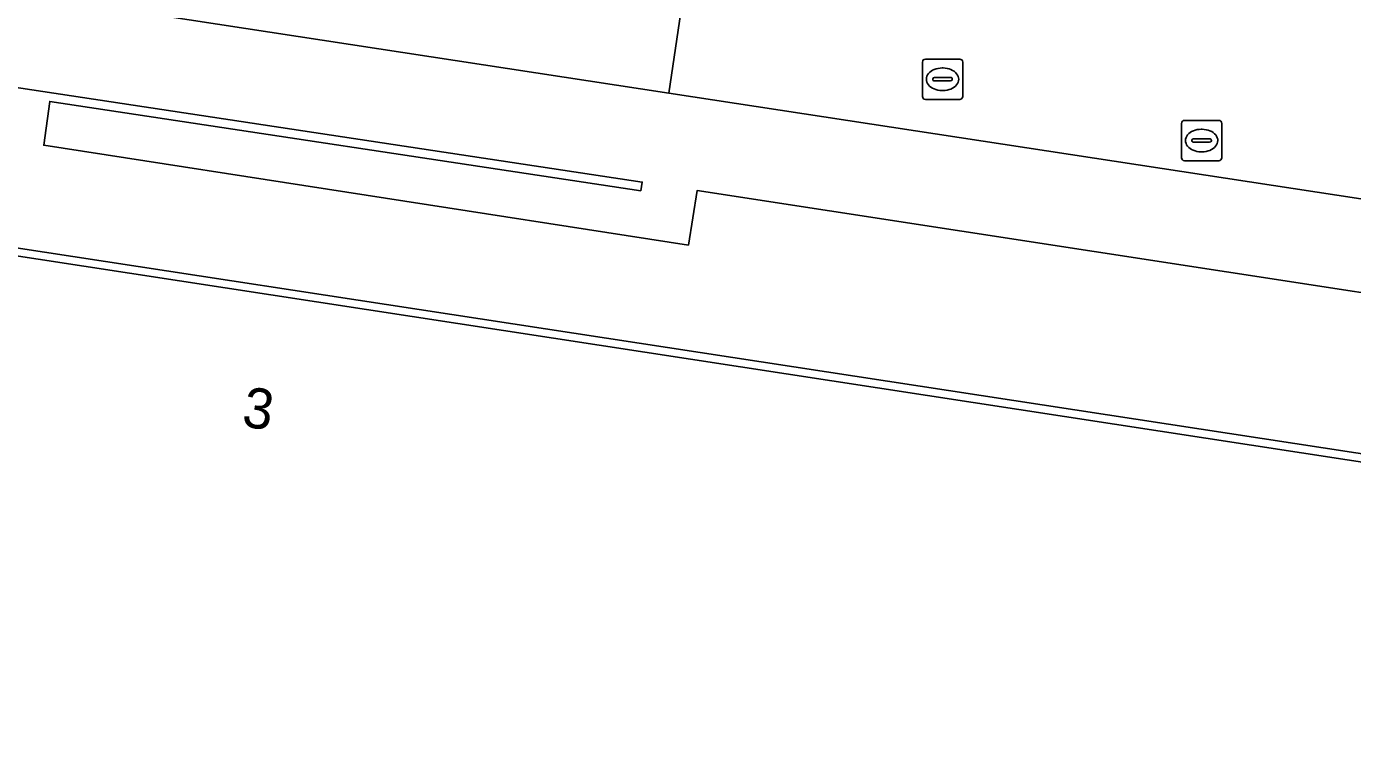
# Model space of a CAD drawing. Extents: x 161090 to 161692, y 379509 to 380907.
# Drawn here: x 161426.27 to 161459.19, y 380421.99 to 380439.9 of the extents above; entities that cross this region are included whole.
import ezdxf

# ---------------------------------------------------------------- set-up
doc = ezdxf.new("R2010")
doc.units = 0
for name, color, linetype in [('IMGEO_Groenvoorziening', 7, 'Continuous'), ('IMGEO_Pand', 7, 'Continuous'), ('IMGEO_Pand_nummerreeks', 7, 'Continuous'), ('IMGEO_Pand_overbouw', 7, 'Continuous'), ('IMGEO_Rioolput', 7, 'Continuous'), ('IMGEO_Voetpad_gesloten', 7, 'Continuous'), ('IMGEO_Voetpad_open', 7, 'Continuous')]:
    doc.layers.add(name, color=color, linetype=linetype)

msp = doc.modelspace()

# ---------------------------------------------------------------- linework, layer by layer
at = {"layer": 'IMGEO_Groenvoorziening'}
msp.add_lwpolyline([(161493.731, 380423.528), (161495.965, 380438.206), (161443.393, 380446.183), (161442.217, 380438.238), (161478.261, 380432.731), (161477.122, 380425.066), (161489.343, 380423.181), (161491.526, 380422.852)], dxfattribs=at)
at = {"layer": 'IMGEO_Pand'}
msp.add_lwpolyline([(161415.881, 380435.194), (161415.964, 380435.735), (161391.176, 380439.506), (161383.009, 380385.949), (161464.836, 380373.488), (161472.988, 380426.991), (161418.398, 380435.368), (161418.318, 380434.848)], dxfattribs=at)
at = {"layer": 'IMGEO_Pand_overbouw'}
msp.add_lwpolyline([(161458.223, 380370.06), (161464.36, 380369.123), (161473.226, 380427.168), (161391.017, 380439.754), (161382.131, 380381.674), (161399.864, 380378.968), (161426.096, 380374.964), (161453.543, 380370.774)], close=True, dxfattribs=at)
msp.add_lwpolyline([(161418.318, 380434.848), (161418.398, 380435.368), (161472.988, 380426.991), (161464.836, 380373.488), (161383.009, 380385.949), (161391.176, 380439.506), (161415.964, 380435.735), (161415.881, 380435.194)], dxfattribs=at)
at = {"layer": 'IMGEO_Rioolput'}
for p, q in [((161448.512, 380438.16), (161448.512, 380439.012)), ((161448.587, 380439.086), (161449.439, 380439.086)), ((161449, 380438.866), (161449.025, 380438.866)), ((161449.513, 380439.012), (161449.513, 380438.16)), ((161448.771, 380438.58), (161448.771, 380438.592)), ((161449.209, 380438.543), (161448.811, 380438.543)), ((161448.814, 380438.629), (161449.212, 380438.629)), ((161449.255, 380438.592), (161449.255, 380438.58)), ((161449.023, 380438.306), (161448.998, 380438.306)), ((161449.439, 380438.086), (161448.587, 380438.086)), ((161454.944, 380436.637), (161454.944, 380437.489)), ((161455.019, 380437.563), (161455.871, 380437.563)), ((161455.945, 380437.489), (161455.945, 380436.637)), ((161455.432, 380437.343), (161455.457, 380437.343)), ((161455.203, 380437.057), (161455.203, 380437.069)), ((161455.641, 380437.02), (161455.243, 380437.02)), ((161455.246, 380437.106), (161455.644, 380437.106)), ((161455.455, 380436.783), (161455.43, 380436.783)), ((161455.687, 380437.069), (161455.687, 380437.057)), ((161455.871, 380436.563), (161455.019, 380436.563))]:
    msp.add_line(p, q, dxfattribs=at)
for points in [[(161448.512, 380438.16), (161448.512, 380439.012)], [(161448.587, 380439.086), (161449.439, 380439.086)], [(161449.513, 380439.012), (161449.513, 380438.16)], [(161449.439, 380438.086), (161448.587, 380438.086)], [(161454.944, 380436.637), (161454.944, 380437.489)], [(161455.019, 380437.563), (161455.871, 380437.563)], [(161455.945, 380437.489), (161455.945, 380436.637)], [(161455.871, 380436.563), (161455.019, 380436.563)]]:
    msp.add_lwpolyline(points, dxfattribs=at)
for centre, radius, start, end in [((161448.589, 380439.01), 0.0765, 91.552, 178.448), ((161448.589, 380439.01), 0.0765, 91.552, 178.448), ((161449.437, 380439.01), 0.0765, 1.552, 88.448), ((161449.437, 380439.01), 0.0765, 1.552, 88.448), ((161448.811, 380438.589), 0.0403, 85.8775, 175.7526), ((161448.808, 380438.579), 0.0366, 178.938, 274.7102), ((161449.212, 380438.586), 0.043, 264.8664, 352.4533), ((161449.216, 380438.591), 0.0386, 1.7309, 96.639), ((161448.589, 380438.162), 0.0765, 181.552, 268.448), ((161448.589, 380438.162), 0.0765, 181.552, 268.448), ((161449.437, 380438.162), 0.0765, 271.552, 358.448), ((161449.437, 380438.162), 0.0765, 271.552, 358.448), ((161455.021, 380437.487), 0.0765, 91.552, 178.448), ((161455.021, 380437.487), 0.0765, 91.552, 178.448), ((161455.869, 380437.487), 0.0765, 1.552, 88.448), ((161455.869, 380437.487), 0.0765, 1.552, 88.448), ((161455.243, 380437.066), 0.0403, 85.8775, 175.7526), ((161455.24, 380437.056), 0.0366, 178.938, 274.7102), ((161455.644, 380437.063), 0.043, 264.8664, 352.4533), ((161455.648, 380437.068), 0.0386, 1.7309, 96.639), ((161455.021, 380436.639), 0.0765, 181.552, 268.448), ((161455.021, 380436.639), 0.0765, 181.552, 268.448), ((161455.869, 380436.639), 0.0765, 271.552, 358.448), ((161455.869, 380436.639), 0.0765, 271.552, 358.448)]:
    msp.add_arc(centre, radius, start, end, dxfattribs=at)
for centre, major_axis, ratio, start_param, end_param in [((161448.999, 380438.586), (-0.387, 0.002), 0.722429, 4.712389, 7.853982), ((161449.024, 380438.586), (-0.39, 0.002), 0.717154, 1.570796, 4.712389), ((161455.431, 380437.063), (-0.387, 0.002), 0.722429, 4.712389, 7.853982), ((161455.456, 380437.063), (-0.39, 0.002), 0.717154, 1.570796, 4.712389)]:
    msp.add_ellipse(centre, major_axis=major_axis, ratio=ratio, start_param=start_param, end_param=end_param, dxfattribs=at)
at = {"layer": 'IMGEO_Voetpad_gesloten'}
msp.add_lwpolyline([(161408.715, 380456.21), (161409.175, 380459.263), (161409.326, 380460.065), (161407.756, 380460.303), (161407.057, 380455.696), (161406.698, 380453.806), (161406.57, 380452.878), (161406.436, 380451.901), (161405.596, 380445.799), (161405.292, 380443.896), (161442.217, 380438.238), (161443.393, 380446.183), (161443.671, 380448.06), (161443.979, 380450.12), (161444.743, 380454.689), (161442.833, 380454.979), (161442.709, 380453.98), (161442.237, 380450.876)], dxfattribs=at)
msp.add_lwpolyline([(161376.251, 380448.346), (161375.894, 380446.054), (161375.235, 380441.827), (161377.808, 380441.418), (161378.471, 380445.674), (161404.319, 380441.69), (161425.407, 380438.468), (161441.558, 380436.032), (161441.518, 380435.817), (161426.845, 380438.036), (161426.695, 380436.945), (161442.702, 380434.464), (161442.92, 380435.825), (161475.669, 380430.786), (161470.633, 380397.978), (161472.927, 380397.636), (161476.304, 380419.814), (161488.559, 380417.958), (161489.343, 380423.181), (161477.122, 380425.066), (161478.261, 380432.731), (161442.217, 380438.238), (161405.292, 380443.896)], close=True, dxfattribs=at)
at = {"layer": 'IMGEO_Voetpad_open'}
for points in [[(161475.669, 380430.786), (161442.92, 380435.825), (161442.702, 380434.464), (161426.695, 380436.945), (161426.845, 380438.036), (161441.518, 380435.817), (161441.558, 380436.032), (161425.407, 380438.468), (161425.207, 380436.998), (161404.093, 380440.226), (161404.319, 380441.69), (161378.471, 380445.674), (161377.808, 380441.418), (161375.516, 380426.06), (161371.977, 380402.925), (161373.421, 380402.686), (161372.216, 380394.847), (161370.769, 380395.064), (161368.855, 380382.814), (161399.728, 380378.077), (161399.864, 380378.968), (161382.131, 380381.674), (161391.017, 380439.754), (161473.226, 380427.168)], [(161418.318, 380434.848), (161418.398, 380435.368), (161472.988, 380426.991), (161464.836, 380373.488), (161383.009, 380385.949), (161391.176, 380439.506), (161415.964, 380435.735), (161415.881, 380435.194)]]:
    msp.add_lwpolyline(points, dxfattribs=at)
msp.add_lwpolyline([(161426.096, 380374.964), (161453.543, 380370.774), (161453.639, 380371.379), (161458.301, 380370.677), (161458.223, 380370.06), (161464.36, 380369.123), (161473.226, 380427.168), (161391.017, 380439.754), (161382.131, 380381.674), (161399.864, 380378.968), (161399.955, 380379.569), (161426.178, 380375.551)], close=True, dxfattribs=at)

# ---------------------------------------------------------------- texts
at = {"layer": 'IMGEO_Pand_nummerreeks'}
msp.add_text('3', height=1, rotation=351.3896, dxfattribs=at).set_placement((161431.587, 380429.969))

doc.saveas('drawing.dxf')
